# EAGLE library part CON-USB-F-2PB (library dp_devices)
USB Female connector with 2 body pins
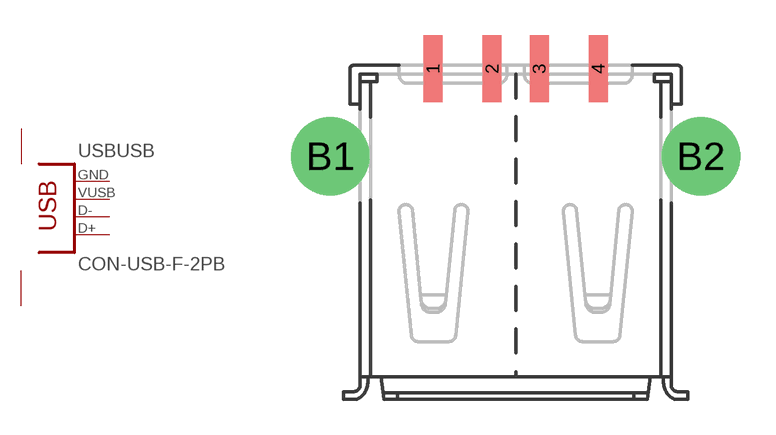
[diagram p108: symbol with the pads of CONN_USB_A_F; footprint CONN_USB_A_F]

Designator prefix USB; gates USB=CONN_USB_4P B=USB_BODY_PINS_2P

## CON-USB-F-2PB  [CONN_USB_A_F]
1  USB:VUSB
2  USB:D-
3  USB:D+
4  USB:GND
B1  B:BODY  hiz
B2  B:BODY  hiz

## Footprint CONN_USB_A_F (pad centres in mm)
USB AF SMD Mfr no. AU-Y1006-2-R Digikey
smd 0.8 x 2.82: 1 -3.5,6.46; 2 -1,6.46; 3 1,6.46; 4 3.5,6.46
drill 2.3 round: B1 -7.85,2.75; B2 7.85,2.75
